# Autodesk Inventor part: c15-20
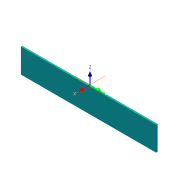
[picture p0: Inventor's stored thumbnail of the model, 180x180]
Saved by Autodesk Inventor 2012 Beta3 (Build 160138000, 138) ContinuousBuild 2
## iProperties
Created: 2011-02
Part Number: c15-20
Material: Default
Document SubType Name: Modeling
Designer: Beta-8540w
Density: 1 g/cm^3
Author: Beta-8540w
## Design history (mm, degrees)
sketch "Sketch1"
  geometry: L1 (-44.45, 7.937)-(44.45, 7.937); L2 (44.45, 7.937)-(44.45, -7.938); L3 (44.45, -7.938)-(-44.45, -7.938); L4 (-44.45, -7.938)-(-44.45, 7.937); 3 further points
  constraints: 8 end point, 2 midpoint, 2 parallel, 1 horizontal, 1 horizontal alignment, 1 perpendicular, 1 vertical alignment
  dimensions: "length" = 88.9 distance of L1.start L1.end; "d1" = 15.875 distance of L3.end L1.start
extrude "Extrusion1" new body sketch "Sketch1" taper "d3" = 0 deg; distance "thickness" = 1
body "Solid1"
other parameters: "d4" = 0, "d5" = 0, "d6" = 0, "d7" = 0, "d8" = 0, "d9" = 0
